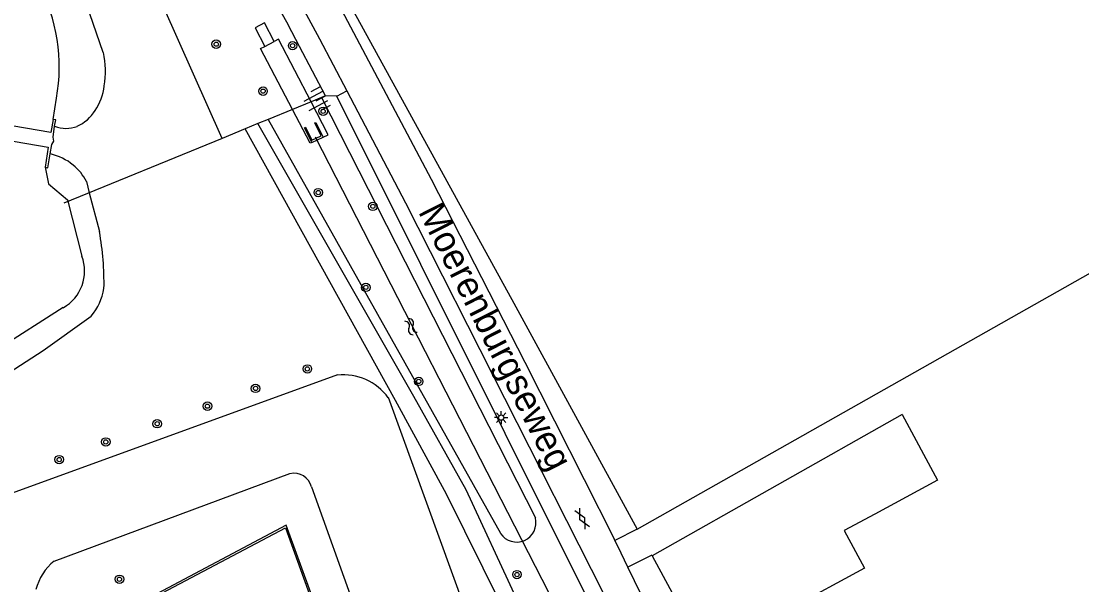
# Model space of a CAD drawing. Extents: x 135999 to 138000, y 396000 to 398501.
# Drawn here: x 136274.6 to 136374.9, y 396525.5 to 396578.8 of the extents above; entities that cross this region are included whole.
import ezdxf

# ---------------------------------------------------------------- set-up
doc = ezdxf.new("R2010")
doc.units = 0
for name, color, linetype in [('gg-afsc-draadraster', 7, 'Continuous'), ('gg-afsc-hekwerk', 7, 'Continuous'), ('gg-afsc-lijn draadraster', 7, 'Continuous'), ('gg-anno-openbare ruimte label', 7, 'Continuous'), ('gg-bbg-bijgebouw', 7, 'Continuous'), ('gg-bbg-gedigitaliseerde bijgebouw', 7, 'Continuous'), ('gg-knt-onverhard', 7, 'Continuous'), ('gg-knt-verharding', 7, 'Continuous'), ('gg-kntw-bovenkant insteek waterloop', 7, 'Continuous'), ('gg-kntw-waterlijn', 7, 'Continuous'), ('gg-kwrk-duiker nz buis', 7, 'Continuous'), ('gg-kwrk-kunstwerk', 7, 'Continuous'), ('gg-kwrk-stuw', 7, 'Continuous'), ('gg-kwrk-uitstroombak niveau min 01', 7, 'Continuous'), ('gt-grn-groengrens', 7, 'Continuous'), ('gt-symb-boom', 7, 'Continuous'), ('gt-symb-gesloten verharding', 7, 'Continuous'), ('gt-symb-lichtmast', 7, 'Continuous'), ('gt-symb-talud symbool', 7, 'Continuous'), ('gt-symb-watersymbool', 7, 'Continuous')]:
    doc.layers.add(name, color=color, linetype=linetype)

# ---------------------------------------------------------------- blocks, each defined once
blk = doc.blocks.new('gt0-BOOM')
at = {"layer": 'gt-symb-boom'}
for radius in [0.4, 0.2]:
    blk.add_circle((0, 0), radius, dxfattribs=at)
blk = doc.blocks.new('gt0-TALUD_1')
at = {"layer": 'gt-symb-talud symbool'}
for p, q in [((-1, -1), (-1, 0)), ((-0.5, -2), (-0.5, 0)), ((0, -1), (0, 0)), ((0.5, -2), (0.5, 0)), ((1, -1), (1, 0))]:
    blk.add_line(p, q, dxfattribs=at)
blk = doc.blocks.new('gt0-WA')
at = {"layer": 'gt-symb-watersymbool'}
for centre, start, end in [((-0.32, 0.02), 28.0725, 151.9275), ((0.43, 0.42), 208.0725, 331.9275), ((-0.32, -0.43), 28.0725, 151.9275), ((0.43, -0.03), 208.0725, 331.9275)]:
    blk.add_arc(centre, 0.425, start, end, dxfattribs=at)
blk = doc.blocks.new('gt0-GESVH1')
at = {"layer": 'gt-symb-gesloten verharding'}
for p, q in [((-0.99, -0.26), (0.01, 0.24)), ((0.01, -0.26), (-0.99, 0.24)), ((0.01, 0.24), (1.01, -0.26)), ((1.01, 0.24), (0.01, -0.26))]:
    blk.add_line(p, q, dxfattribs=at)
blk = doc.blocks.new('gt0-LMAST')
at = {"layer": 'gt-symb-lichtmast'}
for p, q in [((-0.18, 0.17), (-0.45, 0.44)), ((-0.01, 0.25), (-0.01, 0.62)), ((0.17, 0.17), (0.44, 0.44)), ((-0.26, 0), (-0.63, 0)), ((-0.18, -0.18), (-0.45, -0.45)), ((-0.01, -0.25), (-0.01, -0.63)), ((0.44, -0.45), (0.17, -0.18)), ((0.24, 0), (0.62, 0))]:
    blk.add_line(p, q, dxfattribs=at)
blk.add_circle((-0.01, 0), 0.25, dxfattribs=at)

msp = doc.modelspace()

# ---------------------------------------------------------------- linework, layer by layer
at = {"layer": 'gg-afsc-draadraster'}
msp.add_line((136332.85, 396530.77), (136383.96, 396559.67), dxfattribs=at)
for points in [[(136300.63, 396589.63), (136321.21, 396552.14), (136332.85, 396530.77)], [(136317.51, 396520.73), (136320.03, 396523.6), (136314.84, 396534.07), (136310.01, 396542.95), (136295.79, 396568.61)]]:
    msp.add_lwpolyline(points, dxfattribs=at)
at = {"layer": 'gg-afsc-hekwerk'}
for p, q in [((136294.43, 396588.25), (136299.86, 396578.46)), ((136300.94, 396576.4), (136299.86, 396578.46)), ((136303.39, 396571.73), (136300.94, 396576.4)), ((136302.03, 396571.17), (136300.26, 396570.44)), ((136303, 396571.57), (136302.03, 396571.17)), ((136303.39, 396571.73), (136303, 396571.57)), ((136300.26, 396570.44), (136297.96, 396569.5)), ((136297.01, 396569.11), (136295.79, 396568.61)), ((136297.96, 396569.5), (136297.01, 396569.11)), ((136295.79, 396568.61), (136293.62, 396567.72)), ((136293.62, 396567.72), (136278.64, 396561.58))]:
    msp.add_line(p, q, dxfattribs=at)
at = {"layer": 'gg-afsc-lijn draadraster'}
msp.add_lwpolyline([(136300.63, 396589.63), (136321.21, 396552.14), (136332.85, 396530.77)], dxfattribs=at)
at = {"layer": 'gg-bbg-bijgebouw'}
for p, q in [((136357.93, 396541.6), (136334.29, 396528.26)), ((136334.29, 396528.26), (136339.32, 396518.97)), ((136354.37, 396527.09), (136339.32, 396518.97))]:
    msp.add_line(p, q, dxfattribs=at)
at = {"layer": 'gg-bbg-gedigitaliseerde bijgebouw'}
msp.add_lwpolyline([(136357.93, 396541.6), (136361.27, 396535.4), (136355.33, 396532.2), (136352.45, 396530.64), (136354.37, 396527.09)], dxfattribs=at)
at = {"layer": 'gg-knt-onverhard'}
msp.add_line((136334.25, 396528.33), (136331.99, 396527.19), dxfattribs=at)
at = {"layer": 'gg-knt-verharding'}
for p, q in [((136331.03, 396529.16), (136330.76, 396529.71)), ((136331.99, 396527.19), (136331.03, 396529.16)), ((136334.25, 396528.33), (136334.29, 396528.26)), ((136336.66, 396517.62), (136331.99, 396527.19))]:
    msp.add_line(p, q, dxfattribs=at)
for points in [[(136330.76, 396529.71), (136330.68, 396529.88), (136322.28, 396546.52), (136313.42, 396563.82), (136303.79, 396582.01), (136288.46, 396610.26)], [(136296.41, 396589.03), (136302.82, 396577.14), (136305.41, 396572.21)], [(136305.41, 396572.21), (136310.96, 396561.61), (136329.69, 396524.7)]]:
    msp.add_lwpolyline(points, dxfattribs=at)
at = {"layer": 'gg-kntw-bovenkant insteek waterloop'}
for p, q in [((136282.38, 396575.83), (136281.11, 396579.5)), ((136303, 396571.57), (136302.03, 396571.17)), ((136303, 396571.57), (136323.24, 396531.85)), ((136300.26, 396570.44), (136297.96, 396569.5)), ((136297.96, 396569.5), (136319.94, 396530.38)), ((136277.35, 396566.24), (136277.39, 396566.23)), ((136280.79, 396563.63), (136281.06, 396562.57)), ((136281.06, 396562.57), (136282.02, 396558.9)), ((136304.52, 396545.35), (136269.65, 396532.68)), ((136317.51, 396520.73), (136309.34, 396543.21)), ((136277.75, 396527.76), (136300.03, 396536.02)), ((136302.07, 396534.76), (136308.75, 396516.11))]:
    msp.add_line(p, q, dxfattribs=at)
msp.add_lwpolyline([(136261.04, 396537.55), (136276.69, 396547.66), (136281.24, 396550.92)], dxfattribs=at)
for centre, radius, start, end in [((136274.34, 396574.03), 8.25, 350.4994, 12.6477), ((136277.01, 396573.39), 5.51, 326.562, 352.4021), ((136278.34, 396572.34), 3.82, 294.2393, 328.8394), ((136278.85, 396571.65), 2.99, 249.0195, 290.6567), ((136276.29, 396561.28), 5.08, 50.335, 77.4812), ((136276.3, 396561.29), 5.07, 27.5442, 50.3212), ((136256.27, 396554.16), 26.18, 358.6269, 10.4284), ((136277.09, 396554.42), 5.43, 319.7404, 350.5093), ((136305.05, 396540.05), 5.32, 36.364, 95.6558), ((136300.4, 396534.34), 1.72, 14.1807, 102.4224), ((136321.47, 396531.38), 1.83, 213.3919, 14.7554), ((136280.74, 396523.92), 4.86, 128.016, 166.4123)]:
    msp.add_arc(centre, radius, start, end, dxfattribs=at)
at = {"layer": 'gg-kntw-waterlijn'}
for p, q in [((136277.63, 396569.5), (136277.95, 396571.52)), ((136278.59, 396551.72), (136262.03, 396541.17))]:
    msp.add_line(p, q, dxfattribs=at)
msp.add_lwpolyline([(136276.89, 396564.98), (136277.21, 396563.43), (136279.01, 396561.91), (136280.35, 396556.58)], dxfattribs=at)
for centre, radius, start, end in [((136261.52, 396574.48), 16.7, 349.7986, 27.9611), ((136276.63, 396555.17), 3.98, 299.5909, 20.6286)]:
    msp.add_arc(centre, radius, start, end, dxfattribs=at)
at = {"layer": 'gg-kwrk-duiker nz buis'}
msp.add_lwpolyline([(136335.08, 396497.22), (136324.55, 396524.73), (136302.45, 396567.82)], dxfattribs=at)
at = {"layer": 'gg-kwrk-kunstwerk'}
for points in [[(136302.03, 396571.17), (136298.95, 396577.08), (136298.55, 396576.88)], [(136300.26, 396570.44), (136297.26, 396576.2), (136297.66, 396576.41)], [(136303.16, 396567.83), (136303.65, 396568.06), (136302.03, 396571.17)], [(136302.09, 396567.32), (136301.93, 396567.25), (136300.26, 396570.44)], [(136303.35, 396521.04), (136299.68, 396531.15), (136281.38, 396521.44)], [(136290.64, 396514.45), (136292.54, 396509.24), (136292.34, 396509.15), (136293.26, 396506.62), (136293.44, 396506.68), (136296.19, 396499.21), (136310.04, 396502.08), (136312.44, 396495.43), (136292.87, 396491.35), (136281.83, 396521.5), (136299.6, 396530.91), (136303.15, 396521.11), (136290.64, 396514.45)]]:
    msp.add_lwpolyline(points, dxfattribs=at)
at = {"layer": 'gg-kwrk-stuw'}
for points in [[(136277.63, 396569.5), (136277.42, 396568.27), (136264.3, 396570.5), (136264.57, 396571.87)], [(136263.71, 396567.16), (136264.08, 396569.11), (136277.17, 396566.88), (136276.89, 396564.98)], [(136277.35, 396566.24), (136277.5, 396567.14), (136277.7, 396567.46), (136277.63, 396567.83), (136277.78, 396568.86)], [(136277.78, 396568.86), (136277.88, 396569.46), (136277.63, 396569.5)], [(136276.89, 396564.98), (136277.14, 396564.94), (136277.35, 396566.24)]]:
    msp.add_lwpolyline(points, dxfattribs=at)
at = {"layer": 'gg-kwrk-uitstroombak niveau min 01'}
for p, q in [((136297.66, 396576.41), (136298.55, 396576.88)), ((136302.09, 396567.32), (136303.16, 396567.83))]:
    msp.add_line(p, q, dxfattribs=at)
for points in [[(136298.55, 396576.88), (136297.62, 396578.65), (136296.73, 396578.18), (136297.66, 396576.41)], [(136302.09, 396567.32), (136301.41, 396568.72), (136301.5, 396568.76), (136302.09, 396567.55), (136302.99, 396567.97), (136302.4, 396569.19), (136302.49, 396569.23), (136303.16, 396567.83)]]:
    msp.add_lwpolyline(points, dxfattribs=at)
at = {"layer": 'gt-grn-groengrens'}
for p, q in [((136304.46, 396571.72), (136305.41, 396572.21)), ((136304.46, 396571.72), (136303.39, 396571.73)), ((136332.85, 396530.77), (136330.76, 396529.71))]:
    msp.add_line(p, q, dxfattribs=at)
for points in [[(136293.62, 396567.72), (136282.65, 396592.34), (136275.68, 396604.09), (136268.89, 396608.36)], [(136326.02, 396521.7), (136325.59, 396522.82), (136328.33, 396523.91), (136304.46, 396571.72)], [(136318.53, 396519.63), (136321.68, 396522.99), (136321.45, 396524.23), (136316.7, 396534.49), (136311.74, 396543.3), (136297.01, 396569.11)]]:
    msp.add_lwpolyline(points, dxfattribs=at)

# ---------------------------------------------------------------- block references
at = {"layer": 'gt-symb-boom'}
for p in [(136293.06, 396576.62), (136300.28, 396576.48), (136297.49, 396572.18), (136303.17, 396570.28), (136302.71, 396562.59), (136307.87, 396561.29), (136307.21, 396553.63), (136301.68, 396545.92), (136312.21, 396544.74), (136296.78, 396544.08), (136292.23, 396542.4), (136287.48, 396540.74), (136282.62, 396539.02), (136278.21, 396537.35), (136321.5, 396526.48), (136283.91, 396526.04)]:
    msp.add_blockref('gt0-BOOM', p, dxfattribs=at)
at = {"layer": 'gt-symb-gesloten verharding', "rotation": -62.66592414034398}
msp.add_blockref('gt0-GESVH1', (136327.67, 396531.78), dxfattribs=at)
at = {"layer": 'gt-symb-lichtmast'}
msp.add_blockref('gt0-LMAST', (136320.01, 396541.32), dxfattribs=at)
at = {"layer": 'gt-symb-talud symbool', "xscale": 0.9998249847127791, "yscale": 0.999824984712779, "rotation": -62.02527007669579}
msp.add_blockref('gt0-TALUD_1', (136303.39, 396571.73), dxfattribs=at)
at = {"layer": 'gt-symb-watersymbool', "rotation": 122.21189736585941}
msp.add_blockref('gt0-WA', (136311.5, 396549.86), dxfattribs=at)

# ---------------------------------------------------------------- texts
at = {"layer": 'gg-anno-openbare ruimte label'}
msp.add_text('Moerenburgseweg', height=2.5, rotation=296.9, dxfattribs=at).set_placement((136312.12, 396560.79))

doc.saveas('drawing.dxf')
